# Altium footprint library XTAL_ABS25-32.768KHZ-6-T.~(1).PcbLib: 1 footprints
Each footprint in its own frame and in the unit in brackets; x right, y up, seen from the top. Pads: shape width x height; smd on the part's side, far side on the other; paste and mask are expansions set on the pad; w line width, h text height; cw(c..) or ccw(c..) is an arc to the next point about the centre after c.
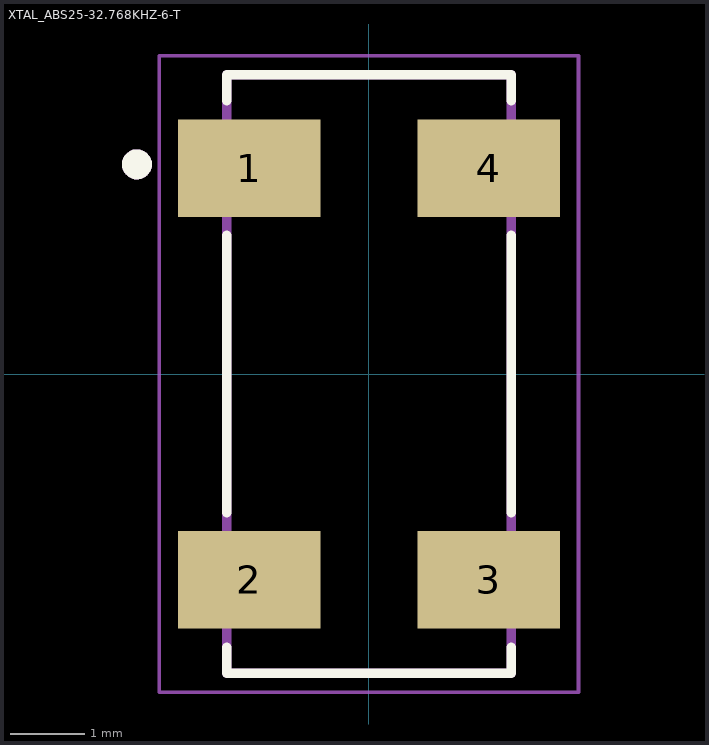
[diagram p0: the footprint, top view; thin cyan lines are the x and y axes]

## XTAL_ABS25-32.768KHZ-6-T [mm]
pads (4):
  rect 1.9x1.3 smd: 1(-1.6,2.75) 2(-1.6,-2.75) 3(1.6,-2.75) 4(1.6,2.75)
Top Overlay:
  circle w0.2: c-3.1,2.8 r0.1
  lines w0.127: -1.9,-3.65 -1.9,-4 1.9,-4 1.9,-3.65 ; -1.9,-1.85 -1.9,1.85 ; -1.9,3.65 -1.9,4 1.9,4 1.9,3.65 ; 1.9,-1.85 1.9,1.85
Assembly Top:
  circle w0.2: c-3.1,2.8 r0.1
  lines w0.127: -1.9,-4 1.9,-4 1.9,4 -1.9,4 -1.9,-4
Courtyard Top:
  lines w0.05: -2.8,-4.25 2.8,-4.25 2.8,4.25 -2.8,4.25 -2.8,-4.25
3D body "step_temp.STEP": height 2, standoff -2, extent -4,-1.25 4,1.408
